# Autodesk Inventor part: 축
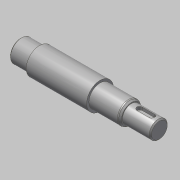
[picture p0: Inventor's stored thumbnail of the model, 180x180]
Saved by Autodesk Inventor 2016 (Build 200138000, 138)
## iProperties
Created: 2016-06
Part Number: 축
Material: 강철, 연강
Document SubType Name: Modeling
Designer: mduedu
Density: 7.86 g/cm^3
Appearance: 강철
Author: mduedu
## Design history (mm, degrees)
sketch "스케치1"
  geometry: L1 (-62, 0)-(62, 0); L2 (-62, 0)-(-62, 10); L3 (-62, 10)-(-45, 10); L4 (-45, 10)-(-45, 12); L5 (-45, 12)-(9, 12); L6 (9, 12)-(9, 10); L7 (9, 10)-(37, 10); L8 (37, 10)-(37, 8); L9 (37, 8)-(62, 8); L10 (62, 8)-(62, 0); 2 further points
  constraints: 20 end point, 5 parallel, 2 perpendicular, 1 coincident, 1 collinear, 1 horizontal, 1 midpoint, 1 vertical
  dimensions: "d0" = 124 distance of L1.start L1.end; "d2" = 16 diameter of L9 L1; "d3" = 20 diameter of L7 L1; "d4" = 24 diameter of L5 L1; "d5" = 20 diameter of L3 L1; "d6" = 17 distance of L2.end L3.end; "d7" = 25 distance of L8.end L9.end; "d8" = 53 distance from line of L5.end L10
revolve "회전1" sketch "스케치1" stored, may be unused: angle "d9" = 90 deg
chamfer "모따기1" distance "d10" = 2; stored, may be unused: second distance "d11" = 2, angle "d12" = 30 deg
fillet "모깎기1" dims "d13" = 2
node "작업 평면1"
sketch "스케치2"
  geometry: L1 (-5, 2.5)-(6, 2.5); L2 (6, -2.5)-(-5, -2.5); L3 (-5, 0)-(6, 0); L4 (-12.5, 8.845)-(-12.5, -8.845) reference; A1 r 2.5 centre (-5, 0) between (-5, 2.5) and (-5, -2.5); A2 r 2.5 centre (6, 0) between (6, -2.5) and (6, 2.5); 1 further point
  constraints: 6 end point, 4 point on circle, 3 tangent, 2 centre point, 2 parallel, 1 horizontal, 1 horizontal alignment
  dimensions: "d14" = 5 distance edge to line of A1 L4; "d15" = 5 distance between parallel lines of L2 L1; "d16" = 16 dimension on A2 A1
extrude "돌출1" cut sketch "스케치2" distance "d17" = 3; taper "d18" = 0 deg
chamfer "모따기2" distance "d19" = 1; stored, may be unused: second distance "d20" = 2, angle "d21" = 30 deg
sketch "스케치3"
  geometry: L1 (-37, -8)-(-61, -8) reference; L2 (-62, -7)-(-62, 7) reference; L3 (-38.5, -8)-(-40, -6.5); L4 (-40, -6.5)-(-40, -8); L5 (-38.5, -8)-(-40, -8); 1 further point
  constraints: 6 end point, 2 point on line, 1 collinear, 1 vertical
  dimensions: "d22" = 45 deg angle of L4 L3; "d23" = 22 distance between parallel lines of L2 L4; "d24" = 3 diameter of L3.start L4
revolve "회전2" stored, may be unused: angle "d25" = 90 deg
node "작업점1"
sketch "스케치4"
  geometry: 1 further point
hole "구멍1" sketch "스케치4" at (0, 0) diameter "d26" = 3.242; stored, may be unused: countersink angle "d30" = 90 deg, drill point angle "d32" = 120 deg; dims "d27" = 8, "d28" = 4, "d29" = 2, "d31" = 11
chamfer "모따기3" distance "d33" = 2; stored, may be unused: second distance "d34" = 2, angle "d35" = 30 deg
node "솔리드1"
